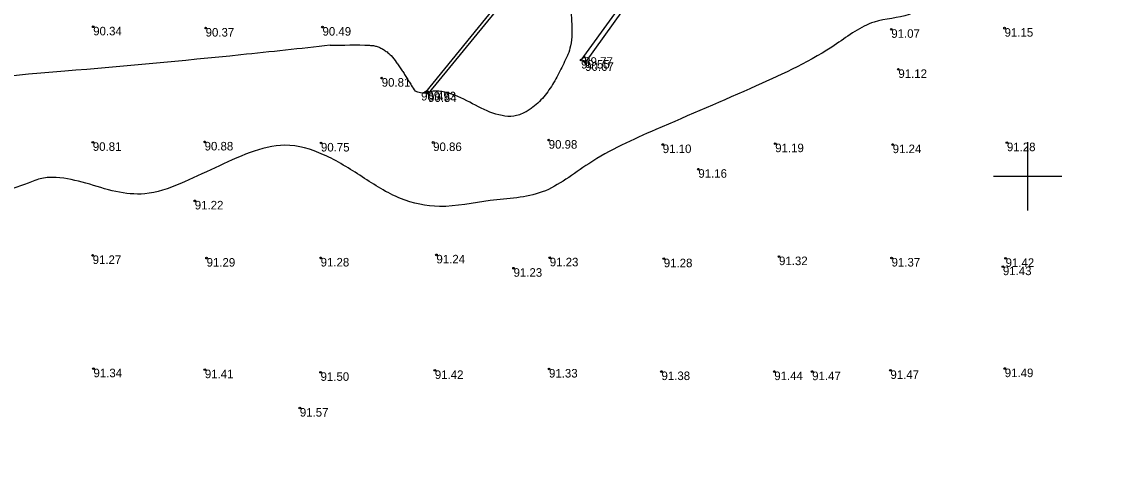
# Model space of a CAD drawing. Extents: x 316000 to 728450, y 314368 to 726000.
# Drawn here: x 726558.9 to 727037.5, y 315870.5 to 316067.8 of the extents above; entities that cross this region are included whole.
import ezdxf

# ---------------------------------------------------------------- set-up
doc = ezdxf.new("R2010")
doc.units = 0
for name, color, linetype in [('GEOD_ELEM_####_####_#', 7, 'Continuous'), ('HIDG_ELEM_####_####_#', 7, 'Continuous'), ('HIDG_GRAV_####_####_#', 7, 'Continuous'), ('RELJ_AATZ_####_TKST_#', 7, 'Continuous'), ('RELJ_ELEM_####_####_#', 7, 'Continuous'), ('RELJ_HORZ_PAMT_####_#', 7, 'Continuous')]:
    doc.layers.add(name, color=color, linetype=linetype)

msp = doc.modelspace()

# ---------------------------------------------------------------- linework, layer by layer
at = {"layer": 'GEOD_ELEM_####_####_#'}
for p, q in [((727000, 316015), (727000, 316000)), ((726985, 316000), (727000, 316000)), ((727000, 316000), (727000, 315985)), ((727000, 316000), (727015, 316000))]:
    msp.add_line(p, q, dxfattribs=at)
at = {"layer": 'HIDG_ELEM_####_####_#'}
for centre in [(726805.55, 316052.28), (726736.8, 316037.11)]:
    msp.add_circle(centre, 0.225, dxfattribs=at)
at = {"layer": 'HIDG_GRAV_####_####_#'}
for points in [[(726736.1, 316036.98), (726866.31, 316197.24)], [(726866.31, 316197.24), (726867.89, 316196.14), (726737.09, 316036.39)], [(726878.01, 316152.77), (726878.91, 316151.79), (726805.97, 316050.03), (726804.2, 316051.06), (726878.01, 316152.77)], [(726736.1, 316036.98), (726737.09, 316036.39)]]:
    msp.add_lwpolyline(points, dxfattribs=at)
at = {"layer": 'RELJ_ELEM_####_####_#'}
for centre in [(726590.23, 316065.64), (726639.53, 316065.1), (726690.79, 316065.51), (726940.23, 316064.55), (726989.91, 316065.04), (726804.2, 316051.06), (726805.55, 316052.28), (726805.97, 316050.03), (726943.34, 316046.95), (726716.76, 316043.11), (726736.1, 316036.98), (726736.8, 316037.11), (726737.09, 316036.39), (726590.06, 316014.92), (726639.09, 316015.11), (726690.11, 316014.65), (726739.31, 316014.85), (726789.99, 316015.89), (726840.01, 316013.95), (726889.32, 316014.34), (726940.84, 316013.93), (726990.93, 316014.77), (726855.62, 316003.12), (726634.78, 315989.21), (726589.99, 315965.27), (726740.75, 315965.52), (726891, 315964.76), (726639.96, 315964.11), (726689.97, 315964.17), (726790.46, 315964.23), (726840.46, 315963.84), (726940.35, 315964.16), (726989.17, 315960.36), (726990.35, 315964), (726774.58, 315959.66), (726590.35, 315915.54), (726639.19, 315915.12), (726689.93, 315913.96), (726740.05, 315914.8), (726790.12, 315915.42), (726839.45, 315914.3), (726888.91, 315914.29), (726905.53, 315914.27), (726939.85, 315914.81), (726989.99, 315915.59), (726680.85, 315898.27)]:
    msp.add_circle(centre, 0.375, dxfattribs=at)
at = {"layer": 'RELJ_HORZ_PAMT_####_#'}
for points in [[(726952.69, 316129.49), (726990.07, 316167.92), (727104.45, 316172.11), (727203.94, 316207.14), (727248.52, 316197.85), (727345.06, 316166.14), (727393.91, 316115.17), (727412.13, 316078.87), (727401.59, 316010.94), (727415.61, 315973.59), (727441.47, 315904.64)], [(726865.4, 316135.38), (726861.46, 316133.99), (726857.53, 316132.46), (726849.72, 316128.96), (726834.35, 316120.15), (726819.49, 316108.79), (726812.31, 316102.12), (726808.79, 316098.52), (726807.05, 316096.65), (726805.33, 316094.74), (726803.43, 316092.29), (726801.99, 316089.77), (726800.25, 316084.54), (726799.73, 316073.62), (726800.13, 316062.62), (726799.54, 316057.29), (726798.38, 316053.42), (726797.81, 316052.17), (726794.41, 316045.26), (726790.63, 316038.7), (726785.92, 316032.85), (726783.03, 316030.32), (726781.42, 316029.18), (726780.58, 316028.63), (726779.7, 316028.12), (726777.19, 316027), (726774.65, 316026.42), (726769.53, 316026.63), (726759.18, 316030.57), (726748.83, 316035.56), (726743.72, 316037.08), (726741.19, 316037.36), (726738.69, 316037.22), (726738.07, 316037.01), (726737.45, 316036.68), (726736.82, 316036.41), (726736.18, 316036.37), (726731.47, 316037.35)], [(727407.26, 315826.81), (727420.88, 315859.78), (727421.31, 315861.98), (727420.84, 315873.16), (727415.63, 315882.87), (727395.8, 315899.43), (727371.45, 315914.61), (727360.58, 315922.6), (727355.76, 315932.78), (727350.87, 315945.8), (727343.65, 315965.03), (727334.62, 315981.5), (727324.71, 316005.53), (727317, 316014.24), (727310.95, 316025.93), (727306.22, 316036.97), (727300.2, 316049.01), (727293.8, 316067.18), (727252.55, 316104.18), (727204.11, 316093.45), (727172.31, 316071.99), (727104.82, 316081.23), (727087.15, 316092.31), (727070.62, 316103.93), (727040.63, 316117.26), (727014.6, 316106.53), (727006.58, 316100.22), (727000.85, 316096.21), (726994.11, 316090.82), (726983.98, 316084.66), (726972.39, 316080.59), (726966.37, 316079.01), (726958.49, 316076.14), (726948.07, 316071.06), (726932.7, 316067.7), (726916.22, 316058.14), (726880.98, 316039.68), (726836.99, 316020.53), (726807.52, 316005.55), (726787.17, 315993.15), (726764.31, 315989.32), (726742.06, 315986.79), (726725.03, 315990.27), (726708.15, 315999.77), (726691.28, 316009.5), (726674.31, 316013.66), (726659.02, 316010.43), (726643.66, 316003.77), (726628.26, 315996.72), (726612.85, 315992.34), (726600.2, 315993.32), (726587.04, 315996.97), (726574, 315999.47), (726567.72, 315999.1), (726561.71, 315997.03), (726548.35, 315992.52), (726536.61, 315988.25), (726525.25, 315984.49), (726513.03, 315977.96), (726485.95, 315966.35), (726456.08, 315949.13), (726439.28, 315937.58), (726388.53, 315922.53), (726290.27, 315916.68), (726240.08, 315917.6), (726226.6, 315921.61), (726211.69, 315923.04), (726191.22, 315924.62), (726136.88, 315919.22), (726111.29, 315920.51), (726086.94, 315922.23)], [(726694.17, 316057.52), (726654.96, 316053.3), (726577.82, 316046.13), (726493.45, 316035.88), (726431.66, 316021.24), (726337.81, 316004.37), (726291.42, 315989.03), (726139.13, 315989.03)], [(726694.17, 316057.52), (726711.46, 316057.52), (726713.13, 316057.37), (726713.96, 316057.19), (726714.79, 316056.97), (726715.6, 316056.67), (726716.39, 316056.31), (726717.93, 316055.41), (726719.46, 316054.28), (726720.85, 316053), (726723.16, 316050.15), (726724.3, 316048.48), (726725.43, 316046.8), (726726.54, 316045.11), (726727.63, 316043.4), (726728.68, 316041.69), (726729.73, 316039.98), (726731.47, 316037.35)]]:
    msp.add_spline(points, degree=3, dxfattribs=at)

# ---------------------------------------------------------------- texts
at = {"layer": 'RELJ_AATZ_####_TKST_#'}
for s, p in [('90.34', (726590.23, 316061.89)), ('90.49', (726690.79, 316061.76)), ('90.37', (726639.53, 316061.35)), ('91.07', (726940.23, 316060.8)), ('91.15', (726989.91, 316061.29)), ('90.55', (726804.2, 316047.31)), ('89.77', (726805.55, 316048.53)), ('90.67', (726805.97, 316046.28)), ('91.12', (726943.34, 316043.2)), ('90.81', (726716.76, 316039.36)), ('90.49', (726734.04, 316033.3)), ('89.73', (726736.8, 316033.36)), ('90.54', (726737.09, 316032.64)), ('90.81', (726590.06, 316011.17)), ('90.88', (726639.09, 316011.36)), ('90.75', (726690.11, 316010.9)), ('90.86', (726739.31, 316011.1)), ('90.98', (726789.99, 316012.14)), ('91.10', (726840.01, 316010.2)), ('91.19', (726889.32, 316010.59)), ('91.24', (726940.84, 316010.18)), ('91.28', (726990.93, 316011.02)), ('91.16', (726855.62, 315999.37)), ('91.22', (726634.78, 315985.46)), ('91.27', (726589.99, 315961.52)), ('91.24', (726740.75, 315961.77)), ('91.29', (726639.96, 315960.36)), ('91.28', (726689.97, 315960.42)), ('91.23', (726790.46, 315960.48)), ('91.28', (726840.46, 315960.09)), ('91.32', (726891, 315961.01)), ('91.37', (726940.35, 315960.41)), ('91.43', (726989.17, 315956.61)), ('91.42', (726990.35, 315960.25)), ('91.23', (726774.58, 315955.91)), ('91.34', (726590.35, 315911.79)), ('91.41', (726639.19, 315911.37)), ('91.50', (726689.93, 315910.21)), ('91.42', (726740.05, 315911.05)), ('91.33', (726790.12, 315911.67)), ('91.38', (726839.45, 315910.55)), ('91.44', (726888.91, 315910.54)), ('91.47', (726905.53, 315910.52)), ('91.47', (726939.85, 315911.06)), ('91.49', (726989.99, 315911.84)), ('91.57', (726680.85, 315894.52))]:
    msp.add_text(s, height=3.75, dxfattribs=at).set_placement(p)

doc.saveas('drawing.dxf')
